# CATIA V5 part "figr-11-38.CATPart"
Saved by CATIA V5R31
Part number: Part1
Bounding box of the stored display mesh (mm): x -177 to 59, y -180 to 60, z 0 to 80
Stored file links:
  D:\PROJECTS\Project 2021\US EDITION\CATIA V5 6R 2021\Resources\Part Files\c11_catia_v5_6r2021_prt\figr-11-38.CATPart
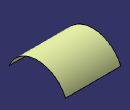
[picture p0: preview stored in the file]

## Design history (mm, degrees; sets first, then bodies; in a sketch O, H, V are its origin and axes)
Set1
  Extrude1: Element1 Sketch1, Lim1 59, Lim2 59, Direction yz-plane
  Scaling1: ToTransfor Extrude1, Reference vertex [face of Extrude1], Ratio 2
Body1 (main body)
  Sketch1 on yz-plane, origin (0, 0, 0), H (0, 1, 0), V (0, 0, 1)
    arc A1 centre (0, -25) radius 65 from (-60, 0) to (60, 0) cw
    point P2 (-60, 0)
    point P3 (60, 0)
    coincidence: P2 H, P3 H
